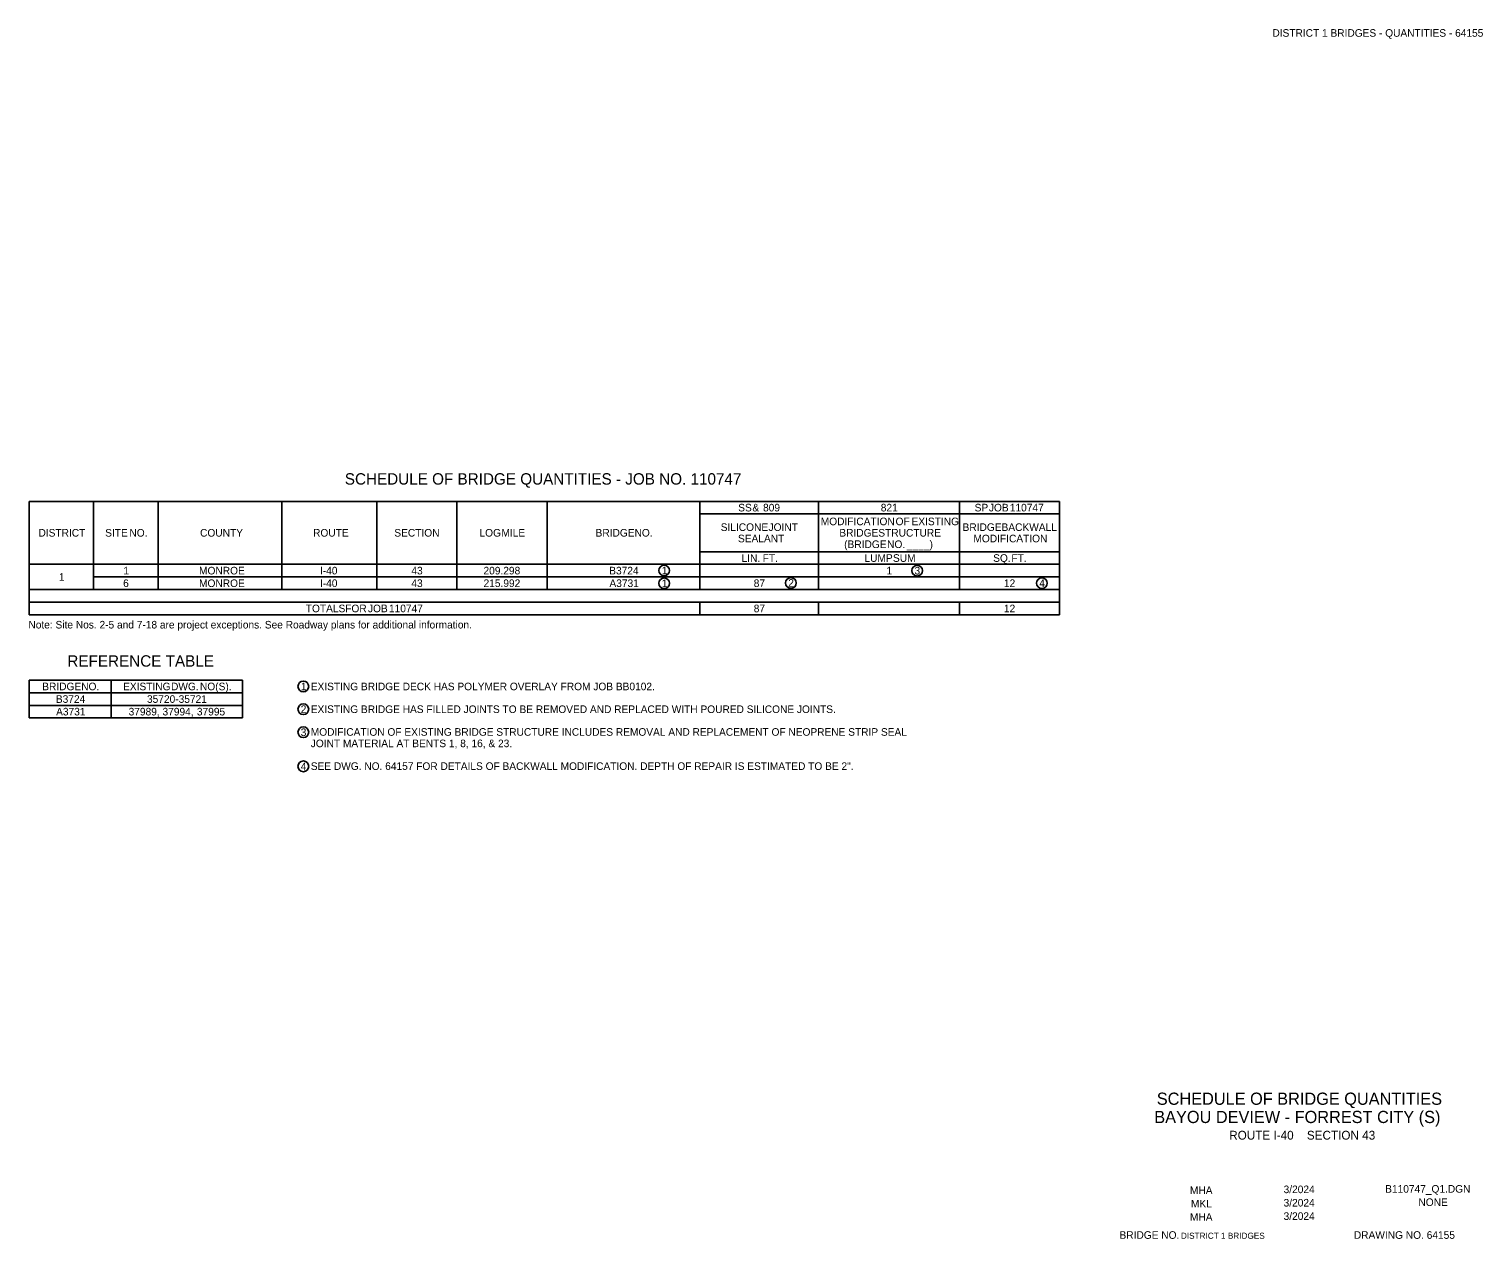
# Model space of a CAD drawing. Extents: x 18 to 1228740, y 11 to 152440.
# Drawn here: x 196.88 to 220.79, y 129.26 to 149.16 of the extents above; entities that cross this region are included whole.
import ezdxf

# ---------------------------------------------------------------- set-up
doc = ezdxf.new("R2010")
doc.units = 0
for name, color, linetype in [('B_Copy In', 7, 'Continuous'), ('B_Dimensions', 7, 'Continuous'), ('B_Text', 7, 'Continuous'), ('B_Title Text', 7, 'Continuous'), ('Default', 7, 'Continuous'), ('E_No Plot', 7, 'Continuous')]:
    doc.layers.add(name, color=color, linetype=linetype)

msp = doc.modelspace()

# ---------------------------------------------------------------- linework, layer by layer
at = {"layer": 'B_Dimensions'}
for centre in [(207.325, 140.256), (211.484, 140.253), (207.325, 140.045), (209.408, 140.051), (213.535, 140.047), (201.392, 138.349), (201.392, 137.974), (201.392, 137.596), (201.392, 137.035)]:
    msp.add_circle(centre, 0.0881, dxfattribs=at)
at = {"layer": 'Default'}
for p, q in [((196.883, 141.393), (213.823, 141.393)), ((196.883, 139.528), (196.883, 141.393)), ((197.943, 139.943), (197.943, 141.393)), ((199.003, 139.943), (199.003, 141.393)), ((201.039, 139.943), (201.039, 141.393)), ((202.599, 139.943), (202.599, 141.393)), ((203.915, 139.943), (203.915, 141.393)), ((205.402, 139.943), (205.402, 141.393)), ((207.912, 139.943), (207.912, 141.393)), ((209.862, 139.943), (209.862, 141.393)), ((212.178, 139.943), (212.178, 141.393)), ((213.823, 139.528), (213.823, 141.393)), ((207.912, 141.186), (213.823, 141.186)), ((207.912, 140.564), (213.823, 140.564)), ((196.883, 140.357), (213.823, 140.357)), ((197.943, 140.15), (213.823, 140.15)), ((196.883, 139.943), (213.823, 139.943)), ((196.883, 139.736), (213.823, 139.736)), ((207.912, 139.528), (207.912, 139.736)), ((209.862, 139.528), (209.862, 139.736)), ((212.178, 139.528), (212.178, 139.736)), ((196.883, 139.528), (213.823, 139.528)), ((196.883, 138.452), (200.393, 138.452)), ((196.883, 137.831), (196.883, 138.452)), ((198.235, 137.831), (198.235, 138.452)), ((200.393, 137.831), (200.393, 138.452)), ((196.883, 138.245), (200.393, 138.245)), ((196.883, 138.038), (200.393, 138.038)), ((196.883, 137.831), (200.393, 137.831))]:
    msp.add_line(p, q, dxfattribs=at)
at = {"layer": 'E_No Plot'}
for p, q in [((196.883, 141.393), (196.883, 141.393)), ((196.883, 138.452), (196.883, 138.452))]:
    msp.add_line(p, q, dxfattribs=at)

# ---------------------------------------------------------------- texts
at = {"layer": 'B_Copy In'}
for s, height, p in [('DISTRICT 1 BRIDGES - QUANTITIES - 64155', 0.1248, (217.325, 149.033)), ('SCHEDULE OF BRIDGE QUANTITIES', 0.2004, (215.424, 131.469)), ('BAYOU DEVIEW - FORREST CITY (S)', 0.2004, (215.383, 131.169)), ('ROUTE I-40', 0.144, (216.615, 130.897)), ('SECTION 43', 0.144, (217.892, 130.897)), ('MHA', 0.125, (215.969, 130.001)), ('3/2024', 0.125, (217.509, 130.016)), ('B110747_Q1.DGN', 0.1248, (219.18, 130.024)), ('MKL', 0.125, (215.986, 129.781)), ('3/2024', 0.125, (217.509, 129.796)), ('NONE', 0.125, (219.726, 129.805)), ('MHA', 0.125, (215.969, 129.561)), ('3/2024', 0.125, (217.509, 129.576)), ('BRIDGE NO. ', 0.125, (214.811, 129.265)), ('DISTRICT 1 BRIDGES', 0.1008, (215.821, 129.265)), ('DRAWING NO. 64155', 0.125, (218.664, 129.265))]:
    msp.add_text(s, height=height, dxfattribs=at).set_placement(p)
at = {"layer": 'B_Text'}
for s, height, p in [('1', 0.125, (207.286, 140.193)), ('3', 0.125, (211.441, 140.19)), ('1', 0.125, (207.286, 139.982)), ('2', 0.125, (209.365, 139.989)), ('4', 0.125, (213.492, 139.985)), ('Note: Site Nos. 2-5 and 7-18 are project exceptions. See Roadway plans for additional information. ', 0.1248, (196.872, 139.302)), ('1', 0.125, (201.352, 138.286)), ('EXISTING BRIDGE DECK HAS POLYMER OVERLAY FROM JOB BB0102.', 0.1248, (201.514, 138.286)), ('2', 0.125, (201.349, 137.912)), ('EXISTING BRIDGE HAS FILLED JOINTS TO BE REMOVED AND REPLACED WITH POURED SILICONE JOINTS.', 0.1248, (201.514, 137.912)), ('3', 0.125, (201.349, 137.533)), ('JOINT MATERIAL AT BENTS 1, 8, 16, & 23.', 0.1248, (201.514, 137.35)), ('MODIFICATION OF EXISTING BRIDGE STRUCTURE INCLUDES REMOVAL AND REPLACEMENT OF NEOPRENE STRIP SEAL ', 0.1248, (201.514, 137.538)), ('4', 0.125, (201.349, 136.972)), ('SEE DWG. NO. 64157 FOR DETAILS OF BACKWALL MODIFICATION. DEPTH OF REPAIR IS ESTIMATED TO BE 2". ', 0.1248, (201.514, 136.976))]:
    msp.add_text(s, height=height, dxfattribs=at).set_placement(p)
at = {"layer": 'B_Title Text'}
for s, p in [('SCHEDULE OF BRIDGE QUANTITIES - JOB NO. 110747', (202.074, 141.668)), ('REFERENCE TABLE', (197.512, 138.674))]:
    msp.add_text(s, height=0.1875, dxfattribs=at).set_placement(p)
at = {"layer": 'Default'}
for s, p in [('SS', (208.542, 141.227)), (' &', (208.729, 141.227)), (' 809', (208.904, 141.227)), ('821', (210.886, 141.227)), ('SP', (212.429, 141.227)), (' JOB', (212.617, 141.227)), (' 110747', (212.961, 141.227)), ('SILICONE', (208.254, 140.906)), (' JOINT', (208.994, 140.906)), ('MODIFICATION', (209.899, 141)), (' OF', (211.083, 141)), (' EXISTING', (211.345, 141)), ('BRIDGE', (212.231, 140.906)), (' BACKWALL', (212.825, 140.906)), ('DISTRICT', (197.037, 140.813)), ('SITE', (198.134, 140.813)), (' NO.', (198.486, 140.813)), ('COUNTY', (199.694, 140.813)), ('ROUTE', (201.552, 140.813)), ('SECTION', (202.888, 140.813)), ('LOG', (204.288, 140.813)), (' MILE', (204.602, 140.813)), ('BRIDGE', (206.197, 140.813)), (' NO.', (206.791, 140.813)), ('SEALANT', (208.538, 140.719)), ('BRIDGE', (210.205, 140.813)), (' STRUCTURE', (210.799, 140.813)), ('MODIFICATION', (212.409, 140.719)), ('(BRIDGE', (210.284, 140.625)), (' NO.', (210.944, 140.625)), (' ____)', (211.27, 140.625)), ('1', (198.433, 140.191)), ('MONROE', (199.677, 140.191)), ('I-40', (201.665, 140.191)), ('43', (203.168, 140.191)), ('209.298', (204.354, 140.191)), ('B3724', (206.421, 140.191)), ('LIN.', (208.597, 140.398)), (' FT.', (208.898, 140.398)), ('LUMP', (210.618, 140.398)), ('1', (210.98, 140.191)), (' SUM', (211.04, 140.398)), ('SQ.', (212.734, 140.398)), (' FT.', (212.987, 140.398)), ('1', (197.373, 140.087)), ('6', (198.429, 139.984)), ('MONROE', (199.677, 139.984)), ('I-40', (201.665, 139.984)), ('43', (203.168, 139.984)), ('215.992', (204.355, 139.984)), ('A3731', (206.425, 139.984)), ('87', (208.797, 139.984)), ('12', (212.911, 139.984)), ('TOTALS', (201.432, 139.569)), (' FOR', (202.034, 139.569)), (' JOB', (202.408, 139.569)), (' 110747', (202.753, 139.569)), ('87', (208.797, 139.569)), ('12', (212.911, 139.569)), ('BRIDGE', (197.099, 138.286)), (' NO.', (197.693, 138.286)), ('EXISTING', (198.428, 138.286)), (' DWG.', (199.17, 138.286)), (' NO(S).', (199.646, 138.286)), ('B3724', (197.323, 138.079)), ('35720-35721', (198.821, 138.079)), ('A3731', (197.327, 137.872)), ('37989,', (198.519, 137.872)), (' 37994,', (199.03, 137.872)), (' 37995', (199.595, 137.872))]:
    msp.add_text(s, height=0.125, dxfattribs=at).set_placement(p)

doc.saveas('drawing.dxf')
